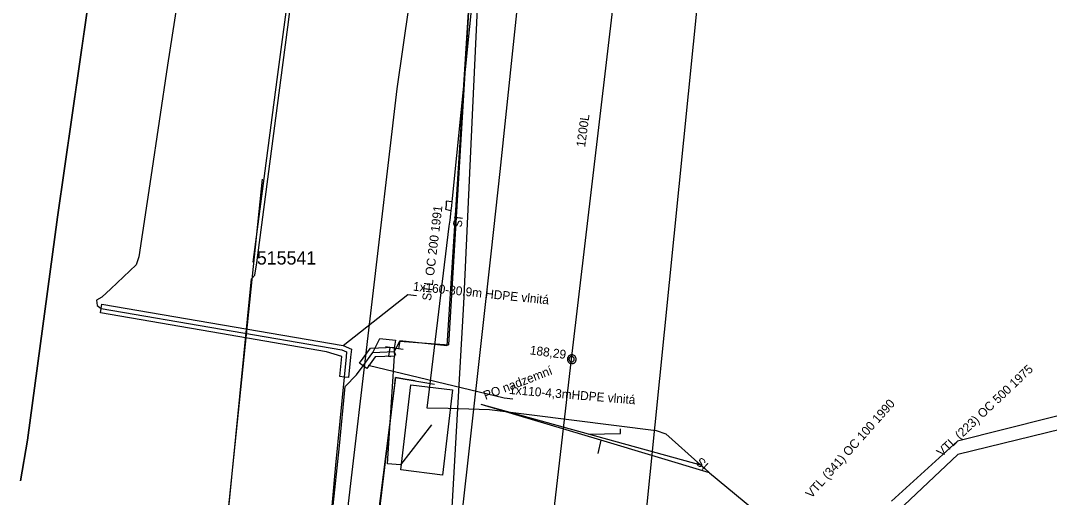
# Model space of a CAD drawing. Extents: x -746464 to -745690, y -1051581 to -1049993.
# Drawn here: x -745879 to -745763.1, y -1050834.1 to -1050780.4 of the extents above; entities that cross this region are included whole.
import ezdxf

# ---------------------------------------------------------------- set-up
doc = ezdxf.new("R2010")
doc.units = 0
for name, color, linetype in [('04_CETIN_neprovozovane', 7, 'Continuous'), ('04_CETIN_sdelovaci_podzem', 7, 'Continuous'), ('45_Eltodo_popisy', 7, 'Continuous'), ('45_Eltodo_vedeni_NN_zemni', 7, 'Continuous'), ('48_Prazs_plynarenska_kabel_PKO', 7, 'Continuous'), ('48_Prazs_plynarenska_STL', 7, 'Continuous'), ('48_Prazs_plynarenska_STL_popisy', 7, 'Continuous'), ('48_Prazs_plynarenska_VTL', 7, 'Continuous'), ('48_Prazs_plynarenska_VTL_popisy', 7, 'Continuous'), ('48_Prazs_plynarenska_VTL_regul_stanice', 7, 'Continuous'), ('51_PVaK_kanal_jednotna_overena poloha_rad', 7, 'Continuous'), ('51_PVaK_kanal_objekty', 7, 'Continuous'), ('51_PVaK_kanal_popisy', 7, 'Continuous'), ('51_PVaK_vodovod_NEPROVOZUJE PVK_neoverene poloha', 7, 'Continuous'), ('55_PREdi_chranicky', 7, 'Continuous'), ('55_PREdi_NN', 7, 'Continuous'), ('55_PREdi_NN_pripojovaci_misto', 7, 'Continuous'), ('55_PREdi_stavby_popisy', 7, 'Continuous'), ('55_PREdi_VN', 7, 'Continuous'), ('55_PREdi_ZRUSENE_elektro', 7, 'Continuous'), ('57_TSK Praha_sdelovaci_optika_orientacni poloha', 7, 'Continuous')]:
    doc.layers.add(name, color=color, linetype=linetype)

msp = doc.modelspace()

# ---------------------------------------------------------------- linework, layer by layer
at = {"layer": '04_CETIN_neprovozovane'}
for points in [[(-745824.99, -1050797.35), (-745808.46, -1050640.08), (-745805.54, -1050612.57), (-745804.51, -1050603.63)], [(-745828.07, -1050790.21), (-745827.33, -1050774.18)], [(-745831.68, -1050857.42), (-745829.08, -1050812.22), (-745828.07, -1050790.21)], [(-745825.99, -1050806.29), (-745824.99, -1050797.35)], [(-745831.68, -1050857.42), (-745825.99, -1050806.29)]]:
    msp.add_lwpolyline(points, dxfattribs=at)
at = {"layer": '04_CETIN_sdelovaci_podzem'}
msp.add_lwpolyline([(-745798.39, -1050529.48), (-745804.32, -1050569.6), (-745807.29, -1050589.25), (-745813.21, -1050629.8), (-745816.05, -1050649.15), (-745817.02, -1050656.79), (-745822.46, -1050693.51), (-745829.82, -1050740.58), (-745836.65, -1050788.06), (-745842.43, -1050837.27), (-745847.37, -1050897.12), (-745848.5, -1050936.02), (-745847.9, -1050962.15), (-745844.68, -1050963.44), (-745846.49, -1050987.64)], dxfattribs=at)
at = {"layer": '45_Eltodo_vedeni_NN_zemni'}
for points in [[(-745852.83, -1050807.58), (-745850.121, -1050787.015), (-745848.595, -1050775.437), (-745847.024, -1050763.51), (-745846.629, -1050760.51), (-745846.956, -1050759.935), (-745846.974, -1050759.9), (-745846.465, -1050759.331), (-745844.922, -1050748.669), (-745843.125, -1050736.245), (-745839.69, -1050712.5)], [(-745858.2, -1050861.33), (-745856.769, -1050847), (-745856.569, -1050845.01), (-745853.016, -1050809.441), (-745852.663, -1050809.048), (-745852.433, -1050807.632), (-745851.079, -1050797.35), (-745849.724, -1050787.067), (-745848.942, -1050781.131), (-745848.162, -1050775.212), (-745848.126, -1050774.94), (-745846.208, -1050760.38), (-745846.402, -1050761.821), (-745846.208, -1050760.38), (-745846.56, -1050759.99)]]:
    msp.add_lwpolyline(points, dxfattribs=at)
at = {"layer": '48_Prazs_plynarenska_kabel_PKO'}
for points in [[(-745832.754, -1050825.878), (-745836.227, -1050830.372), (-745837.713, -1050830.255), (-745836.892, -1050818.13)], [(-745802.4, -1050830.413), (-745815.042, -1050826.929), (-745827.157, -1050823.59)], [(-745801.419, -1050831.282), (-745813.677, -1050827.619), (-745827.157, -1050823.59)], [(-745815.042, -1050826.929), (-745811.458, -1050826.841), (-745811.458, -1050826.347)], [(-745813.677, -1050827.619), (-745814, -1050829.104)]]:
    msp.add_lwpolyline(points, dxfattribs=at)
at = {"layer": '48_Prazs_plynarenska_STL'}
for points in [[(-745812.77, -1050649.64), (-745820.81, -1050703.4), (-745824.07, -1050733.35), (-745827.98, -1050776.17), (-745830.403, -1050800.416)], [(-745830.44, -1050800.76), (-745831.077, -1050800.712), (-745831.1, -1050801.19), (-745831.156, -1050801.614), (-745830.56, -1050801.75)], [(-745830.403, -1050800.416), (-745830.44, -1050800.76), (-745830.496, -1050801.234)], [(-745830.496, -1050801.234), (-745830.56, -1050801.75), (-745830.6, -1050802.13), (-745830.69, -1050802.83), (-745830.77, -1050803.52), (-745833.124, -1050822.814)]]:
    msp.add_lwpolyline(points, dxfattribs=at)
at = {"layer": '48_Prazs_plynarenska_VTL'}
for points in [[(-745733.98, -1050820.3), (-745751.92, -1050822.33), (-745757.83, -1050823.77), (-745773.49, -1050827.72), (-745780.927, -1050834.456)], [(-745833.124, -1050822.814), (-745833.248, -1050823.985), (-745830.872, -1050824.009), (-745826.215, -1050824.152), (-745807.444, -1050826.528), (-745806.327, -1050826.908), (-745802.4, -1050830.413), (-745801.94, -1050830.814), (-745801.419, -1050831.282), (-745792.727, -1050838.442), (-745791.664, -1050837.452), (-745790.23, -1050836.05), (-745789.91, -1050835.79)], [(-745760.077, -1050825.97), (-745773.45, -1050829.22), (-745782.15, -1050837.45), (-745784.87, -1050841.25)]]:
    msp.add_lwpolyline(points, dxfattribs=at)
at = {"layer": '48_Prazs_plynarenska_VTL_regul_stanice'}
msp.add_lwpolyline([(-745830.365, -1050821.924), (-745831.505, -1050831.544), (-745836.195, -1050830.954), (-745835.085, -1050821.364)], close=True, dxfattribs=at)
at = {"layer": '51_PVaK_kanal_jednotna_overena poloha_rad'}
for p, q in [((-745816.96, -1050818.49), (-745811.8, -1050774.88)), ((-745822.51, -1050866.31), (-745816.96, -1050818.49))]:
    msp.add_line(p, q, dxfattribs=at)
at = {"layer": '51_PVaK_kanal_objekty'}
for points in [[(-745816.43, -1050818.5), (-745816.44, -1050818.45), (-745816.44, -1050818.4), (-745816.46, -1050818.35), (-745816.48, -1050818.3), (-745816.5, -1050818.25), (-745816.53, -1050818.21), (-745816.56, -1050818.17), (-745816.6, -1050818.13), (-745816.64, -1050818.1), (-745816.68, -1050818.07), (-745816.73, -1050818.05), (-745816.78, -1050818.03), (-745816.83, -1050818.01), (-745816.88, -1050818.01), (-745816.93, -1050818), (-745816.98, -1050818.01), (-745817.03, -1050818.01), (-745817.08, -1050818.03), (-745817.13, -1050818.05), (-745817.18, -1050818.07), (-745817.22, -1050818.1), (-745817.26, -1050818.13), (-745817.3, -1050818.17), (-745817.33, -1050818.21), (-745817.36, -1050818.25), (-745817.38, -1050818.3), (-745817.4, -1050818.35), (-745817.42, -1050818.4), (-745817.42, -1050818.45), (-745817.43, -1050818.5), (-745817.42, -1050818.55), (-745817.42, -1050818.6), (-745817.4, -1050818.65), (-745817.38, -1050818.7), (-745817.36, -1050818.75), (-745817.33, -1050818.79), (-745817.3, -1050818.83), (-745817.26, -1050818.87), (-745817.22, -1050818.9), (-745817.18, -1050818.93), (-745817.13, -1050818.95), (-745817.08, -1050818.97), (-745817.03, -1050818.99), (-745816.98, -1050818.99), (-745816.93, -1050819), (-745816.88, -1050818.99), (-745816.83, -1050818.99), (-745816.78, -1050818.97), (-745816.73, -1050818.95), (-745816.68, -1050818.93), (-745816.64, -1050818.9), (-745816.6, -1050818.87), (-745816.56, -1050818.83), (-745816.53, -1050818.79), (-745816.5, -1050818.75), (-745816.48, -1050818.7), (-745816.46, -1050818.65), (-745816.44, -1050818.6), (-745816.44, -1050818.55), (-745816.43, -1050818.5)], [(-745816.66, -1050818.49), (-745816.66, -1050818.46), (-745816.666, -1050818.43), (-745816.672, -1050818.4), (-745816.684, -1050818.37), (-745816.702, -1050818.34), (-745816.72, -1050818.316), (-745816.738, -1050818.292), (-745816.762, -1050818.268), (-745816.786, -1050818.25), (-745816.81, -1050818.232), (-745816.84, -1050818.214), (-745816.87, -1050818.202), (-745816.9, -1050818.196), (-745816.93, -1050818.19), (-745816.96, -1050818.19), (-745816.99, -1050818.19), (-745817.02, -1050818.196), (-745817.05, -1050818.202), (-745817.08, -1050818.214), (-745817.11, -1050818.232), (-745817.134, -1050818.25), (-745817.158, -1050818.268), (-745817.182, -1050818.292), (-745817.2, -1050818.316), (-745817.218, -1050818.34), (-745817.236, -1050818.37), (-745817.248, -1050818.4), (-745817.254, -1050818.43), (-745817.26, -1050818.46), (-745817.26, -1050818.49), (-745817.26, -1050818.52), (-745817.254, -1050818.55), (-745817.248, -1050818.58), (-745817.236, -1050818.61), (-745817.218, -1050818.64), (-745817.2, -1050818.664), (-745817.182, -1050818.688), (-745817.158, -1050818.712), (-745817.134, -1050818.73), (-745817.11, -1050818.748), (-745817.08, -1050818.766), (-745817.05, -1050818.778), (-745817.02, -1050818.784), (-745816.99, -1050818.79), (-745816.96, -1050818.79), (-745816.93, -1050818.79), (-745816.9, -1050818.784), (-745816.87, -1050818.778), (-745816.84, -1050818.766), (-745816.81, -1050818.748), (-745816.786, -1050818.73), (-745816.762, -1050818.712), (-745816.738, -1050818.688), (-745816.72, -1050818.664), (-745816.702, -1050818.64), (-745816.684, -1050818.61), (-745816.672, -1050818.58), (-745816.666, -1050818.55), (-745816.66, -1050818.52), (-745816.66, -1050818.49)]]:
    msp.add_lwpolyline(points, dxfattribs=at)
at = {"layer": '51_PVaK_vodovod_NEPROVOZUJE PVK_neoverene poloha'}
msp.add_line((-745828.479, -1051034.728), (-745784.302, -1050594.304), dxfattribs=at)
at = {"layer": '55_PREdi_chranicky'}
for points in [[(-745869.96, -1050812.78), (-745869.875, -1050812.287), (-745842.706, -1050816.957), (-745841.763, -1050817.369), (-745841.863, -1050818.282), (-745842.093, -1050820.55), (-745842.59, -1050820.5), (-745843.087, -1050820.45), (-745842.857, -1050818.178), (-745844.588, -1050817.679), (-745856.52, -1050815.598), (-745870.045, -1050813.273), (-745869.96, -1050812.78)], [(-745840.44, -1050819.24), (-745840.843, -1050818.944), (-745839.601, -1050817.25), (-745836.961, -1050817.14), (-745836.94, -1050817.64), (-745836.919, -1050818.14), (-745839.079, -1050818.23), (-745840.037, -1050819.536), (-745840.44, -1050819.24)]]:
    msp.add_lwpolyline(points, close=True, dxfattribs=at)
at = {"layer": '55_PREdi_NN'}
for points in [[(-745836.931, -1050817.668), (-745836.324, -1050816.464), (-745830.778, -1050816.886), (-745827.386, -1050759.99), (-745822.137, -1050702.889), (-745815.492, -1050657.507), (-745814.201, -1050647.382), (-745837.743, -1050644.622), (-745844.217, -1050648.308), (-745855.524, -1050644.404), (-745855.787, -1050644.26), (-745855.941, -1050644.04), (-745855.971, -1050643.649), (-745855.783, -1050643.337), (-745855.387, -1050643.182), (-745855.006, -1050643.158), (-745854.396, -1050643.244), (-745840.902, -1050645.172), (-745840.316, -1050641.071)], [(-745854.403, -1050643.244), (-745855.633, -1050643.226), (-745855.524, -1050644.404), (-745844.217, -1050648.308), (-745837.743, -1050644.622), (-745814.201, -1050647.382), (-745818.785, -1050683.329), (-745822.137, -1050702.889), (-745827.386, -1050759.99), (-745831.018, -1050816.98), (-745836.308, -1050816.415), (-745836.441, -1050817.331)], [(-745849.34, -1050938.08), (-745850.24, -1050930.51), (-745850.36, -1050926.93), (-745849.98, -1050916.51), (-745849.4, -1050906.5), (-745848.72, -1050895.18), (-745847.78, -1050881.61), (-745847.17, -1050870.78), (-745846.29, -1050858.01), (-745845.23, -1050848.99), (-745844.15, -1050838.16), (-745843.11, -1050828.24), (-745842.45, -1050821.55), (-745841.2, -1050820.27), (-745840.44, -1050819.24), (-745839.34, -1050817.74), (-745838.553, -1050816.181), (-745836.8, -1050816.344), (-745836.935, -1050817.249)], [(-745835.948, -1050817.412), (-745836.441, -1050817.331), (-745836.935, -1050817.249), (-745837.428, -1050817.168), (-745837.921, -1050817.087)], [(-745837.428, -1050817.168), (-745837.509, -1050817.662)], [(-745849.34, -1050938.08), (-745850.24, -1050930.51), (-745850.36, -1050926.93), (-745849.98, -1050916.51), (-745849.4, -1050906.5), (-745848.72, -1050895.18), (-745847.78, -1050881.61), (-745847.17, -1050870.78), (-745846.29, -1050858.01), (-745845.23, -1050848.99), (-745844.15, -1050838.16), (-745843.11, -1050828.24), (-745842.45, -1050821.55), (-745841.2, -1050820.27), (-745840.44, -1050819.24), (-745839.34, -1050817.74), (-745836.94, -1050817.64), (-745836.81, -1050818.03)]]:
    msp.add_lwpolyline(points, dxfattribs=at)
at = {"layer": '55_PREdi_NN_pripojovaci_misto'}
for p, q in [((-745837.834, -1050818.117), (-745837.34, -1050818.195)), ((-745837.509, -1050817.662), (-745837.587, -1050818.156))]:
    msp.add_line(p, q, dxfattribs=at)
at = {"layer": '55_PREdi_stavby_popisy'}
for points in [[(-745842.706, -1050816.957), (-745835.409, -1050811.215), (-745834.414, -1050811.316)], [(-745839.866, -1050819.168), (-745824.568, -1050822.856), (-745823.572, -1050822.938)]]:
    msp.add_lwpolyline(points, dxfattribs=at)
at = {"layer": '55_PREdi_VN'}
for points in [[(-745855.096, -1050674.719), (-745860.553, -1050705.66), (-745865.414, -1050736.68), (-745874.863, -1050802.491), (-745878.253, -1050827.61)], [(-745860.4, -1050771.86), (-745862.47, -1050785.39), (-745864.37, -1050797.99), (-745865.7, -1050806.97), (-745866.03, -1050807.88), (-745868.86, -1050810.57), (-745869.87, -1050811.5), (-745870.47, -1050811.86), (-745870.42, -1050812.45), (-745869.96, -1050812.78), (-745842.85, -1050817.44), (-745842.3, -1050817.68), (-745842.36, -1050818.23), (-745842.59, -1050820.5), (-745843.57, -1050830.43), (-745844.39, -1050839.57)], [(-745860.4, -1050771.86), (-745862.47, -1050785.39), (-745864.37, -1050797.99), (-745865.7, -1050806.97), (-745866.03, -1050807.88), (-745868.86, -1050810.57), (-745869.87, -1050811.5), (-745870.47, -1050811.86), (-745870.42, -1050812.45), (-745869.96, -1050812.78), (-745842.85, -1050817.44), (-745842.3, -1050817.68), (-745842.36, -1050818.23), (-745842.59, -1050820.5), (-745843.57, -1050830.43), (-745844.39, -1050839.57)], [(-745878.253, -1050827.61), (-745879.041, -1050832.177)]]:
    msp.add_lwpolyline(points, dxfattribs=at)
at = {"layer": '55_PREdi_ZRUSENE_elektro'}
for points in [[(-745879.041, -1050832.177), (-745878.253, -1050827.61), (-745874.863, -1050802.491), (-745870.138, -1050769.586), (-745865.414, -1050736.68), (-745860.553, -1050705.66), (-745855.956, -1050680.259), (-745855.096, -1050674.719), (-745850.681, -1050644.993), (-745850.333, -1050642.652), (-745844.55, -1050638.192), (-745843.911, -1050632.622)], [(-745847.256, -1050934.02), (-745846.949, -1050900.459), (-745840.692, -1050853.136), (-745836.879, -1050821.332), (-745836.802, -1050820.568), (-745832.387, -1050821.291)], [(-745834.57, -1050820.933), (-745835.783, -1050820.735), (-745836.802, -1050820.568), (-745840.934, -1050853.104)]]:
    msp.add_lwpolyline(points, dxfattribs=at)
at = {"layer": '57_TSK Praha_sdelovaci_optika_orientacni poloha'}
msp.add_lwpolyline([(-745866.915, -1051055.215), (-745864.415, -1050989.902), (-745858.085, -1050859.426), (-745851.786, -1050798.238)], dxfattribs=at)

# ---------------------------------------------------------------- texts
at = {"layer": '45_Eltodo_popisy'}
msp.add_text('515541', height=1.5, dxfattribs=at).set_placement((-745852.422, -1050807.837))
at = {"layer": '48_Prazs_plynarenska_STL_popisy'}
for s, rotation, p in [('STL OC 200 1991', 83.0439, (-745832.807, -1050811.957)), ('IS', 263, (-745830.189, -1050802.329))]:
    msp.add_text(s, height=1, rotation=rotation, dxfattribs=at).set_placement(p)
at = {"layer": '48_Prazs_plynarenska_VTL_popisy'}
for s, rotation, p in [('PO nadzemní', 21, (-745826.657, -1050823.09)), ('VTL (223) OC 500 1975', 43.4098, (-745775.241, -1050829.538)), ('VTL (341) OC 100 1990', 48.33847, (-745789.939, -1050834.213)), ('IS', 138, (-745801.44, -1050830.314))]:
    msp.add_text(s, height=1, rotation=rotation, dxfattribs=at).set_placement(p)
at = {"layer": '51_PVaK_kanal_popisy'}
for s, rotation, p in [('1200L', 82.25131, (-745815.441, -1050794.666)), ('188,29', 352.49622, (-745821.701, -1050817.937))]:
    msp.add_text(s, height=1, rotation=rotation, dxfattribs=at).set_placement(p)
at = {"layer": '55_PREdi_stavby_popisy'}
for s, rotation, p in [('1x160-30.9m HDPE vlnitá', 354.19605, (-745834.86, -1050810.769)), ('1x110-4,3mHDPE vlnitá', 355.29643, (-745824.029, -1050822.399))]:
    msp.add_text(s, height=1, rotation=rotation, dxfattribs=at).set_placement(p)

doc.saveas('drawing.dxf')
